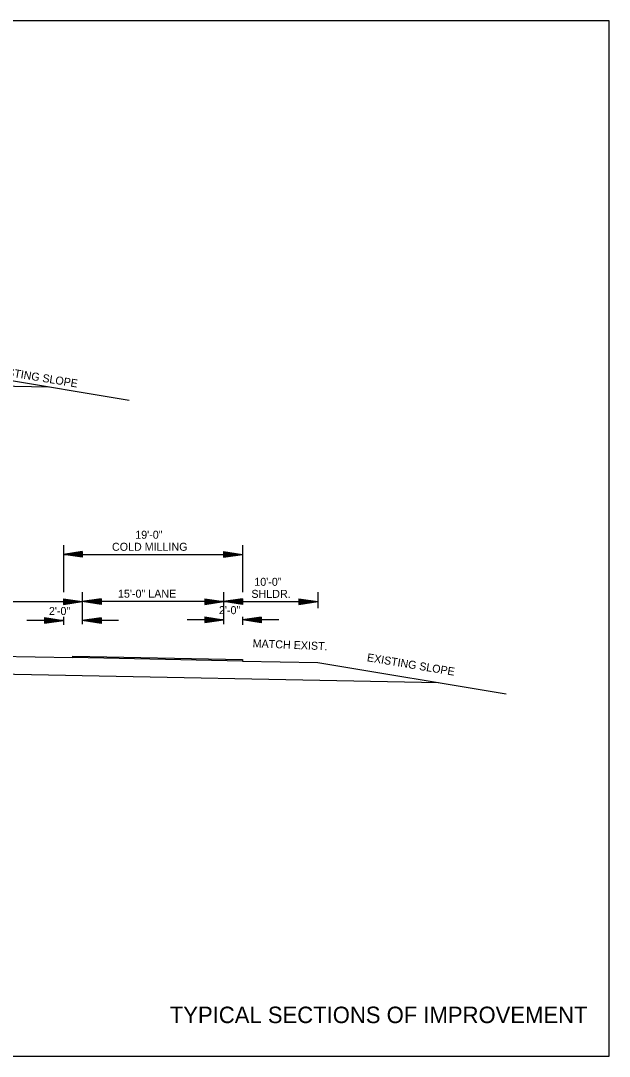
# Model space of a CAD drawing. Extents: x 2261938 to 2263136, y -3124572 to -3124216.
# Drawn here: x 2262261.2 to 2262323.7, y -3124556.1 to -3124446.1 of the extents above; entities that cross this region are included whole.
import ezdxf

# ---------------------------------------------------------------- set-up
doc = ezdxf.new("R2010")
doc.units = 0
for name, color, linetype in [('DSN_DRFT_Common-Annotations', 7, 'Continuous'), ('DSN_DRFT_Common-Line', 7, 'Continuous'), ('DSN_DRFT_Dimension', 7, 'Continuous'), ('SHET_Border-Text', 7, 'Continuous')]:
    doc.layers.add(name, color=color, linetype=linetype)

msp = doc.modelspace()

# ---------------------------------------------------------------- linework, layer by layer
at = {"layer": 'DSN_DRFT_Common-Line'}
for p, q in [((2262252.76, -3124483.08), (2262272.76, -3124486.41)), ((2262218.76, -3124484.08), (2262264.18, -3124484.98)), ((2262265.76, -3124501.8), (2262265.76, -3124506.82)), ((2262284.76, -3124501.8), (2262284.76, -3124506.82)), ((2262267.76, -3124506.82), (2262267.76, -3124510.19)), ((2262282.76, -3124506.82), (2262282.76, -3124510.19)), ((2262292.76, -3124506.8), (2262292.76, -3124508.5)), ((2262265.76, -3124509.42), (2262265.76, -3124510.26)), ((2262284.76, -3124509.42), (2262284.76, -3124510.26)), ((2262245.76, -3124513.34), (2262266.76, -3124513.76)), ((2262218.76, -3124514.68), (2262305.58, -3124516.41)), ((2262284.76, -3124514.12), (2262292.76, -3124514.28)), ((2262292.76, -3124514.28), (2262312.76, -3124517.61))]:
    msp.add_line(p, q, dxfattribs=at)
for points in [[(2262153.71, -3124446.1), (2262153.71, -3124556.1), (2262323.71, -3124556.1), (2262323.71, -3124446.1)], [(2262284.76, -3124514.12), (2262266.76, -3124513.76), (2262266.76, -3124513.76), (2262266.76, -3124513.76), (2262266.76, -3124513.59), (2262266.76, -3124513.59), (2262266.76, -3124513.59), (2262284.76, -3124513.97), (2262284.76, -3124513.97), (2262284.76, -3124514.12)]]:
    msp.add_lwpolyline(points, close=True, dxfattribs=at)
at = {"layer": 'DSN_DRFT_Dimension'}
for p, q in [((2262267.76, -3124502.5), (2262265.76, -3124502.8)), ((2262267.76, -3124502.55), (2262266.09, -3124502.8)), ((2262267.76, -3124502.6), (2262266.44, -3124502.8)), ((2262267.76, -3124502.65), (2262266.77, -3124502.8)), ((2262267.76, -3124502.5), (2262267.76, -3124503.1)), ((2262282.76, -3124502.5), (2262284.76, -3124502.8)), ((2262282.76, -3124502.5), (2262282.76, -3124503.1)), ((2262282.76, -3124502.55), (2262284.43, -3124502.8)), ((2262282.76, -3124502.6), (2262284.08, -3124502.8)), ((2262282.76, -3124502.65), (2262283.75, -3124502.8)), ((2262265.76, -3124502.8), (2262284.76, -3124502.8)), ((2262267.76, -3124503.1), (2262265.76, -3124502.8)), ((2262267.76, -3124503.05), (2262266.09, -3124502.8)), ((2262267.76, -3124503), (2262266.44, -3124502.8)), ((2262267.76, -3124502.95), (2262266.77, -3124502.8)), ((2262267.76, -3124502.7), (2262267.11, -3124502.8)), ((2262267.76, -3124502.9), (2262267.11, -3124502.8)), ((2262267.76, -3124502.75), (2262267.44, -3124502.8)), ((2262267.76, -3124502.85), (2262267.44, -3124502.8)), ((2262282.76, -3124502.7), (2262283.41, -3124502.8)), ((2262282.76, -3124502.75), (2262283.08, -3124502.8)), ((2262282.76, -3124503.1), (2262284.76, -3124502.8)), ((2262282.76, -3124502.9), (2262283.41, -3124502.8)), ((2262282.76, -3124503), (2262284.08, -3124502.8)), ((2262282.76, -3124503.05), (2262284.43, -3124502.8)), ((2262282.76, -3124502.95), (2262283.75, -3124502.8)), ((2262282.76, -3124502.85), (2262283.08, -3124502.8)), ((2262242.76, -3124507.8), (2262267.76, -3124507.8)), ((2262265.76, -3124507.5), (2262267.76, -3124507.8)), ((2262265.76, -3124507.5), (2262265.76, -3124508.1)), ((2262265.76, -3124507.55), (2262267.42, -3124507.8)), ((2262265.76, -3124507.6), (2262267.08, -3124507.8)), ((2262265.76, -3124507.65), (2262266.75, -3124507.8)), ((2262265.76, -3124507.7), (2262266.41, -3124507.8)), ((2262265.76, -3124507.75), (2262266.07, -3124507.8)), ((2262265.76, -3124508.1), (2262267.76, -3124507.8)), ((2262265.76, -3124507.9), (2262266.41, -3124507.8)), ((2262265.76, -3124508), (2262267.08, -3124507.8)), ((2262265.76, -3124508.05), (2262267.42, -3124507.8)), ((2262265.76, -3124507.95), (2262266.75, -3124507.8)), ((2262265.76, -3124507.85), (2262266.07, -3124507.8)), ((2262269.76, -3124507.5), (2262267.76, -3124507.8)), ((2262282.76, -3124507.8), (2262267.76, -3124507.8)), ((2262269.76, -3124508.1), (2262267.76, -3124507.8)), ((2262269.76, -3124507.55), (2262268.09, -3124507.8)), ((2262269.76, -3124508.05), (2262268.09, -3124507.8)), ((2262269.76, -3124507.6), (2262268.44, -3124507.8)), ((2262269.76, -3124508), (2262268.44, -3124507.8)), ((2262269.76, -3124507.65), (2262268.77, -3124507.8)), ((2262269.76, -3124507.95), (2262268.77, -3124507.8)), ((2262269.76, -3124507.7), (2262269.11, -3124507.8)), ((2262269.76, -3124507.9), (2262269.11, -3124507.8)), ((2262269.76, -3124507.75), (2262269.44, -3124507.8)), ((2262269.76, -3124507.85), (2262269.44, -3124507.8)), ((2262269.76, -3124507.5), (2262269.76, -3124508.1)), ((2262280.76, -3124507.5), (2262282.76, -3124507.8)), ((2262280.76, -3124507.5), (2262280.76, -3124508.1)), ((2262280.76, -3124507.55), (2262282.42, -3124507.8)), ((2262280.76, -3124507.6), (2262282.08, -3124507.8)), ((2262280.76, -3124507.65), (2262281.75, -3124507.8)), ((2262280.76, -3124507.7), (2262281.41, -3124507.8)), ((2262280.76, -3124507.75), (2262281.07, -3124507.8)), ((2262280.76, -3124508.1), (2262282.76, -3124507.8)), ((2262280.76, -3124507.9), (2262281.41, -3124507.8)), ((2262280.76, -3124508), (2262282.08, -3124507.8)), ((2262280.76, -3124508.05), (2262282.42, -3124507.8)), ((2262280.76, -3124507.95), (2262281.75, -3124507.8)), ((2262280.76, -3124507.85), (2262281.07, -3124507.8)), ((2262284.76, -3124507.5), (2262282.76, -3124507.8)), ((2262282.76, -3124507.8), (2262292.76, -3124507.8)), ((2262284.76, -3124508.1), (2262282.76, -3124507.8)), ((2262284.76, -3124507.55), (2262283.09, -3124507.8)), ((2262284.76, -3124508.05), (2262283.09, -3124507.8)), ((2262284.76, -3124507.6), (2262283.44, -3124507.8)), ((2262284.76, -3124508), (2262283.44, -3124507.8)), ((2262284.76, -3124507.65), (2262283.77, -3124507.8)), ((2262284.76, -3124507.95), (2262283.77, -3124507.8)), ((2262284.76, -3124507.7), (2262284.11, -3124507.8)), ((2262284.76, -3124507.9), (2262284.11, -3124507.8)), ((2262284.76, -3124507.75), (2262284.44, -3124507.8)), ((2262284.76, -3124507.85), (2262284.44, -3124507.8)), ((2262284.76, -3124507.5), (2262284.76, -3124508.1)), ((2262290.76, -3124507.5), (2262292.76, -3124507.8)), ((2262290.76, -3124507.5), (2262290.76, -3124508.1)), ((2262290.76, -3124507.55), (2262292.42, -3124507.8)), ((2262290.76, -3124507.6), (2262292.08, -3124507.8)), ((2262290.76, -3124507.65), (2262291.75, -3124507.8)), ((2262290.76, -3124507.7), (2262291.41, -3124507.8)), ((2262290.76, -3124507.75), (2262291.07, -3124507.8)), ((2262290.76, -3124508.1), (2262292.76, -3124507.8)), ((2262290.76, -3124507.9), (2262291.41, -3124507.8)), ((2262290.76, -3124508), (2262292.08, -3124507.8)), ((2262290.76, -3124508.05), (2262292.42, -3124507.8)), ((2262290.76, -3124507.95), (2262291.75, -3124507.8)), ((2262290.76, -3124507.85), (2262291.07, -3124507.8)), ((2262265.76, -3124509.8), (2262261.89, -3124509.8)), ((2262263.76, -3124509.5), (2262265.76, -3124509.8)), ((2262263.76, -3124509.5), (2262263.76, -3124510.1)), ((2262263.76, -3124509.55), (2262265.42, -3124509.8)), ((2262263.76, -3124509.6), (2262265.08, -3124509.8)), ((2262263.76, -3124509.65), (2262264.75, -3124509.8)), ((2262263.76, -3124509.7), (2262264.41, -3124509.8)), ((2262263.76, -3124509.75), (2262264.07, -3124509.8)), ((2262263.76, -3124510.1), (2262265.76, -3124509.8)), ((2262263.76, -3124509.9), (2262264.41, -3124509.8)), ((2262263.76, -3124510), (2262265.08, -3124509.8)), ((2262263.76, -3124510.05), (2262265.42, -3124509.8)), ((2262263.76, -3124509.95), (2262264.75, -3124509.8)), ((2262263.76, -3124509.85), (2262264.07, -3124509.8)), ((2262269.76, -3124509.52), (2262267.76, -3124509.82)), ((2262269.76, -3124510.12), (2262267.76, -3124509.82)), ((2262271.62, -3124509.82), (2262267.76, -3124509.82)), ((2262269.76, -3124509.57), (2262268.09, -3124509.82)), ((2262269.76, -3124510.07), (2262268.09, -3124509.82)), ((2262269.76, -3124509.62), (2262268.44, -3124509.82)), ((2262269.76, -3124510.02), (2262268.44, -3124509.82)), ((2262269.76, -3124509.67), (2262268.77, -3124509.82)), ((2262269.76, -3124509.97), (2262268.77, -3124509.82)), ((2262269.76, -3124509.72), (2262269.11, -3124509.82)), ((2262269.76, -3124509.92), (2262269.11, -3124509.82)), ((2262269.76, -3124509.77), (2262269.44, -3124509.82)), ((2262269.76, -3124509.87), (2262269.44, -3124509.82)), ((2262269.76, -3124509.52), (2262269.76, -3124510.12)), ((2262282.76, -3124509.73), (2262278.89, -3124509.73)), ((2262280.76, -3124509.43), (2262282.76, -3124509.73)), ((2262280.76, -3124509.43), (2262280.76, -3124510.03)), ((2262280.76, -3124509.48), (2262282.42, -3124509.73)), ((2262280.76, -3124509.53), (2262282.08, -3124509.73)), ((2262280.76, -3124509.58), (2262281.75, -3124509.73)), ((2262280.76, -3124509.63), (2262281.41, -3124509.73)), ((2262280.76, -3124509.68), (2262281.07, -3124509.73)), ((2262280.76, -3124510.03), (2262282.76, -3124509.73)), ((2262280.76, -3124509.83), (2262281.41, -3124509.73)), ((2262280.76, -3124509.93), (2262282.08, -3124509.73)), ((2262280.76, -3124509.98), (2262282.42, -3124509.73)), ((2262280.76, -3124509.88), (2262281.75, -3124509.73)), ((2262280.76, -3124509.77), (2262281.07, -3124509.73)), ((2262286.76, -3124509.45), (2262284.76, -3124509.75)), ((2262286.76, -3124510.05), (2262284.76, -3124509.75)), ((2262288.62, -3124509.75), (2262284.76, -3124509.75)), ((2262286.76, -3124509.5), (2262285.09, -3124509.75)), ((2262286.76, -3124510), (2262285.09, -3124509.75)), ((2262286.76, -3124509.55), (2262285.44, -3124509.75)), ((2262286.76, -3124509.95), (2262285.44, -3124509.75)), ((2262286.76, -3124509.6), (2262285.77, -3124509.75)), ((2262286.76, -3124509.9), (2262285.77, -3124509.75)), ((2262286.76, -3124509.65), (2262286.11, -3124509.75)), ((2262286.76, -3124509.84), (2262286.11, -3124509.75)), ((2262286.76, -3124509.7), (2262286.44, -3124509.75)), ((2262286.76, -3124509.79), (2262286.44, -3124509.75)), ((2262286.76, -3124509.45), (2262286.76, -3124510.05))]:
    msp.add_line(p, q, dxfattribs=at)

# ---------------------------------------------------------------- texts
at = {"layer": 'DSN_DRFT_Common-Annotations'}
for s, rotation, p in [('EXISTING SLOPE', 350.538, (2262257.94, -3124483.53)), ('MATCH EXIST.', 357.7094, (2262285.84, -3124512.66)), ('EXISTING SLOPE', 350.538, (2262297.94, -3124514.13))]:
    msp.add_text(s, height=0.85, rotation=rotation, dxfattribs=at).set_placement(p)
for s, p in [('19\'-0"', (2262273.39, -3124501.13)), ('COLD MILLING', (2262270.92, -3124502.41)), ('10\'-0"', (2262286.03, -3124506.13)), ('15\'-0" LANE', (2262271.56, -3124507.39)), ('SHLDR.', (2262285.72, -3124507.41)), (' 2\'-0"', (2262263.91, -3124509.23)), (' 2\'-0"', (2262281.96, -3124509.14))]:
    msp.add_text(s, height=0.85, dxfattribs=at).set_placement(p)
at = {"layer": 'SHET_Border-Text'}
msp.add_text('TYPICAL SECTIONS OF IMPROVEMENT', height=1.75, dxfattribs=at).set_placement((2262277.06, -3124552.58))

doc.saveas('drawing.dxf')
